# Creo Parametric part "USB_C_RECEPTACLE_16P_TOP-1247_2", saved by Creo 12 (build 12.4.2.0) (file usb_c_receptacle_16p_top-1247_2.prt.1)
Units: Custom; MM, KILOGRAM, SECS

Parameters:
  PTC_WM_ITERATION = "0"
  PTC_WM_VERSION = "-.0"
  PTC_WM_LIFECYCLE_STATE = "In Work"
  PTC_WM_LIFECYCLE = "MO_CADDocument"
  PTC_WM_CREATED_BY = "Maximilian Roepper (Z0017RMS: MO)"
  PTC_WM_CREATED_ON = "18-Sep-26 11:36:42 AM"
  PTC_WM_MODIFIED_BY = "Maximilian Roepper (Z0017RMS: MO)"
  PTC_WM_MODIFIED_ON = "18-Sep-26 11:36:46 AM"
  PDMLINKNUMBER = "PDM000071455258"
  PTC_WM_NAME = "usb_c_receptacle_16p_top-1247_2.prt"
  PTC_WM_NUMBER = "PDM000071455258"

Other parameters: WEIGHT, WEIGHT_FACTOR, WEIGHT_ADD, _MASS_TEMP, _DIFF_TEMP, MC_ERRORS, SUPPLIER

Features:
  1. coordinate system
  2. datum plane "PRT_YZ"
  3. datum plane "PRT_XY"
  4. datum plane "PRT_XZ"
  5. coordinate system
  6. datum axis
  7. datum axis
  8. datum axis
  9. coordinate system
  10. imported feature
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
Other named items: PRT, SIEMENS_MO, DRW_VIEW_ORG, PRT_X, PRT_Y, PRT_Z, CS0, ROUGH_GROB

Layers: 00_STD_CSYS-KSYS, 01_STD_PLANES-EBENEN, 02_STD_AXES-ACHSEN, 03_STD_CSYS-KSYS, 24_IMPORT_FEAT-IMPORT_KE

Surfaces: 6 plane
